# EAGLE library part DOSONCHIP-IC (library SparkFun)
DOSonCHIP IC This is the tested schematic and footprint for the DOSonCHIP FAT16 FAT32 IC. Spark Fun Electronics SKU : IC-DOSonCHIP. QFN package also tested/proven.
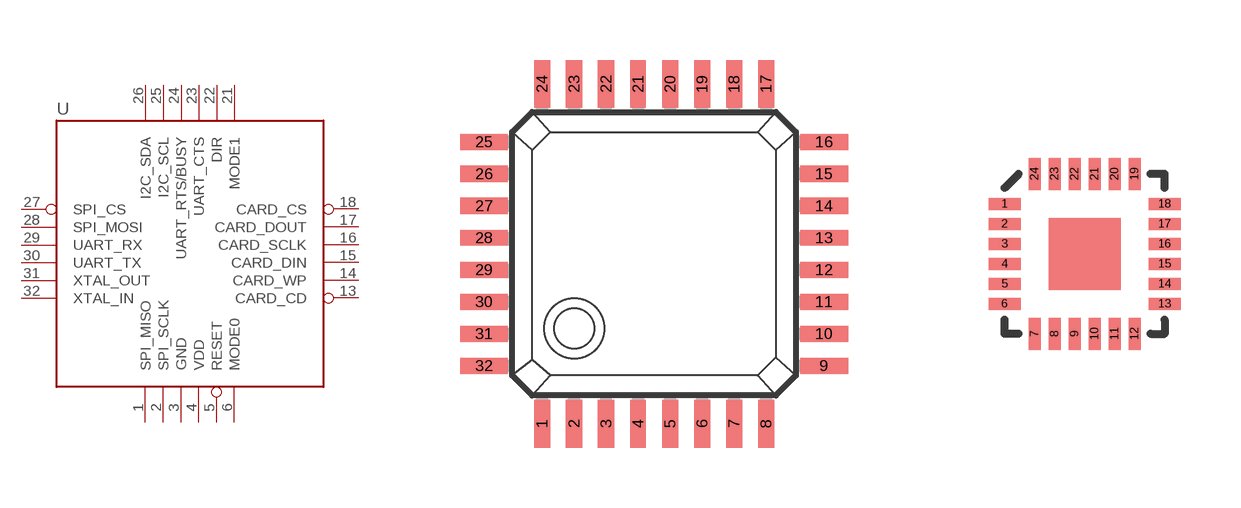
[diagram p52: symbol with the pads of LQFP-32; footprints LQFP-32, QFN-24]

Designator prefix -

## DOSONCHIP-ICLQFP  [LQFP-32]
1  SPI_MISO  out
2  SPI_SCLK  in
3  GND  in
4  VDD  in
5  RESET  in
6  MODE0  in
13  CARD_CD  in
14  CARD_WP  in
15  CARD_DIN
16  CARD_SCLK  out
17  CARD_DOUT  out
18  CARD_CS  in
21  MODE1  in
22  DIR  in
23  UART_CTS  in
24  UART_RTS/BUSY  out
25  I2C_SCL
26  I2C_SDA
27  SPI_CS  in
28  SPI_MOSI  in
29  UART_RX  in
30  UART_TX  out
31  XTAL_OUT  out
32  XTAL_IN  in

## DOSONCHIP-ICQFN  [QFN-24]
1  SPI_MISO  out
2  SPI_SCLK  in
3  GND  in
4  VDD  in
5  RESET  in
6  MODE0  in
7  CARD_CD  in
8  CARD_WP  in
9  CARD_DIN
10  CARD_SCLK  out
11  CARD_DOUT  out
12  CARD_CS  in
13  MODE1  in
14  DIR  in
15  UART_CTS  in
16  UART_RTS/BUSY  out
17  I2C_SCL
18  I2C_SDA
19  SPI_CS  in
20  SPI_MOSI  in
21  UART_RX  in
22  UART_TX  out
23  XTAL_OUT  out
24  XTAL_IN  in

## Footprint LQFP-32 (pad centres in mm)
Quad Flat Package 32 LD LQFP Source: ds232b12.pdf http://www.ftdichip.com
smd 0.4 x 1.2: 1 -2.8,-4.25; 2 -2,-4.25; 3 -1.2,-4.25; 4 -0.4,-4.25; 5 0.4,-4.25; 6 1.2,-4.25; 7 2,-4.25; 8 2.8,-4.25; 17 2.8,4.25; 18 2,4.25; 19 1.2,4.25; 20 0.4,4.25; 21 -0.4,4.25; 22 -1.2,4.25; 23 -2,4.25; 24 -2.8,4.25
smd 1.2 x 0.4: 9 4.25,-2.8; 10 4.25,-2; 11 4.25,-1.2; 12 4.25,-0.4; 13 4.25,0.4; 14 4.25,1.2; 15 4.25,2; 16 4.25,2.8; 25 -4.25,2.8; 26 -4.25,2; 27 -4.25,1.2; 28 -4.25,0.4; 29 -4.25,-0.4; 30 -4.25,-1.2; 31 -4.25,-2; 32 -4.25,-2.8

## Footprint QFN-24 (pad centres in mm)
smd 0.8 x 0.3: 1 -2.5,1.75; 2 -2.5,1.25; 3 -2.5,0.75; 4 -2.5,0.25; 5 -2.5,-0.25; 6 -2.5,-0.75; 13 1.5,-0.75; 14 1.5,-0.25; 15 1.5,0.25; 16 1.5,0.75; 17 1.5,1.25; 18 1.5,1.75
smd 0.3 x 0.8: 7 -1.75,-1.5; 8 -1.25,-1.5; 9 -0.75,-1.5; 10 -0.25,-1.5; 11 0.25,-1.5; 12 0.75,-1.5; 19 0.75,2.5; 20 0.25,2.5; 21 -0.25,2.5; 22 -0.75,2.5; 23 -1.25,2.5; 24 -1.75,2.5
